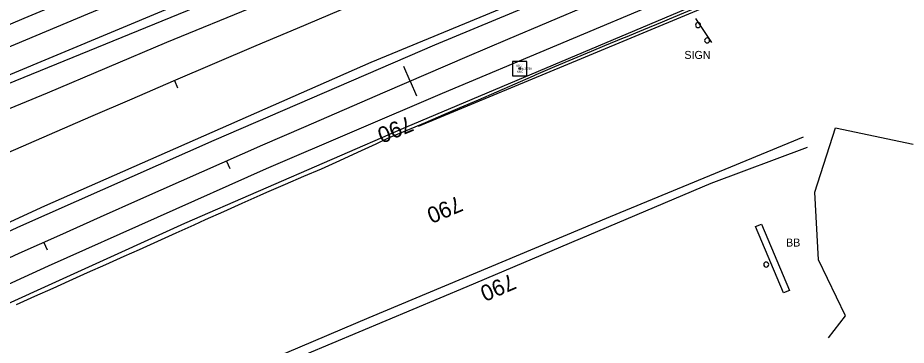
# Model space of a CAD drawing. Extents: x 1901471 to 1963503, y 756461 to 799997.
# Drawn here: x 1905145.4 to 1905589.4, y 758694.4 to 758857.7 of the extents above; entities that cross this region are included whole.
import ezdxf

# ---------------------------------------------------------------- set-up
doc = ezdxf.new("R2010")
doc.units = 0
for name, color, linetype in [('Default', 7, 'Continuous'), ('RD_DTM_BkLn1', 7, 'Continuous'), ('RD_EX_Bldg', 7, 'Continuous'), ('RD_EX_Driveway', 7, 'Continuous'), ('RD_EX_Fence_Other', 7, 'Continuous'), ('RD_EX_GuardRail', 7, 'Continuous'), ('RD_EX_Road', 7, 'Continuous'), ('RD_EX_Road_txCode', 7, 'Continuous'), ('RD_EX_VEG', 7, 'Continuous'), ('RD_HC_Cl', 7, 'Continuous'), ('RD_HC_Data_Tic', 7, 'Continuous'), ('RD_HC_Survey', 7, 'Continuous'), ('RD_HC_TX_Sta50', 7, 'Continuous'), ('RD_HC_txCode', 7, 'Continuous'), ('RD_SMD_Locator', 7, 'Continuous')]:
    doc.layers.add(name, color=color, linetype=linetype)

# ---------------------------------------------------------------- blocks, each defined once
blk = doc.blocks.new('SIGNPOST')
at = {"layer": 'Default'}
for start, end in [(90, 270), (270, 90)]:
    blk.add_arc((0, 0), 0.127, start, end, dxfattribs=at)

msp = doc.modelspace()

# ---------------------------------------------------------------- linework, layer by layer
at = {"layer": 'RD_DTM_BkLn1'}
for points in [[(1905449.13, 758848.09), (1905458.37, 758851.93), (1905467.6, 758855.76), (1905471.12, 758857.23), (1905480.35, 758861.07), (1905489.59, 758864.92), (1905493.47, 758866.54), (1905502.71, 758870.34), (1905511.96, 758874.14), (1905516.47, 758876), (1905525.76, 758879.7), (1905535.05, 758883.4), (1905535.64, 758883.63), (1905544.9, 758887.39), (1905554.17, 758891.15), (1905561.63, 758894.17), (1905570.9, 758897.93), (1905580.17, 758901.69), (1905582.87, 758902.78), (1905592.15, 758906.51)], [(1905144.82, 758714.65), (1905153.93, 758718.76), (1905163.05, 758722.87), (1905171.15, 758726.51), (1905180.29, 758730.58), (1905189.42, 758734.65), (1905198.55, 758738.72), (1905206.29, 758742.17), (1905215.41, 758746.27), (1905224.52, 758750.38), (1905233.64, 758754.49), (1905239.26, 758757.02), (1905248.39, 758761.11), (1905257.51, 758765.2), (1905266.64, 758769.29), (1905269.98, 758770.79), (1905279.17, 758774.72), (1905288.37, 758778.64), (1905297.26, 758782.43), (1905306.35, 758786.59), (1905315.44, 758790.74), (1905324.54, 758794.9), (1905330.78, 758797.75), (1905339.99, 758801.66), (1905349.19, 758805.56), (1905358.4, 758809.47), (1905366.46, 758812.88), (1905375.63, 758816.87), (1905384.8, 758820.86), (1905393.97, 758824.85), (1905403.14, 758828.84), (1905404.56, 758829.46), (1905413.78, 758833.35), (1905422.99, 758837.24), (1905432.2, 758841.13), (1905438.8, 758843.91), (1905448.07, 758847.66), (1905449.13, 758848.09)]]:
    msp.add_lwpolyline(points, dxfattribs=at)
at = {"layer": 'RD_EX_Bldg'}
msp.add_lwpolyline([(1905484.19, 758857.44), (1905492.11, 758845.44)], dxfattribs=at)
msp.add_lwpolyline([(1905517.07, 758754.76), (1905531.02, 758721.64), (1905528.15, 758720.43), (1905514.19, 758753.55)], close=True, dxfattribs=at)
at = {"layer": 'RD_EX_Driveway'}
for points in [[(1905537.99, 758798.17), (1905441.53, 758758.34), (1905320.85, 758708.08), (1905169.69, 758643.9), (1905069.4, 758600.83)], [(1904608.49, 758434.92), (1904740.93, 758494.18), (1904812.91, 758530.05), (1904856.1, 758551.52), (1904903.37, 758573.84), (1904943.2, 758586.31), (1904968.63, 758592.19), (1905001.98, 758596.27), (1905029.09, 758594.83), (1905056.2, 758590.99), (1905068.68, 758592.43), (1905168.49, 758639.1), (1905262.06, 758678.45), (1905370.03, 758723.67), (1905491.92, 758775.14), (1905540.15, 758793.25)]]:
    msp.add_lwpolyline(points, dxfattribs=at)
at = {"layer": 'RD_EX_Fence_Other'}
msp.add_lwpolyline([(1904922.24, 758713.27), (1904940.51, 758722.99), (1904969.08, 758737.95), (1904998.03, 758751.56), (1905043.12, 758770.41), (1905087.82, 758789.75), (1905130.58, 758808.21), (1905160.31, 758820.26), (1905219.98, 758845.62), (1905264.68, 758863.89), (1905325.31, 758888.28), (1905382.84, 758911.8), (1905443.08, 758935.02), (1905504.3, 758959.12), (1905562.41, 758981.56), (1905623.24, 759004.3), (1905713.03, 759039.19), (1905817.39, 759078.93), (1905890.66, 759107.4), (1906024.74, 759158.14)], dxfattribs=at)
at = {"layer": 'RD_EX_GuardRail'}
msp.add_lwpolyline([(1905345.67, 758803.68), (1905429.1, 758838.31), (1905538.42, 758883.79), (1905619.41, 758916.58), (1905717.53, 758955.5), (1905817.23, 758994.07), (1905933.89, 759038.76), (1906032.02, 759075.57), (1906133.29, 759113.62), (1906265.7, 759165.13), (1906336.89, 759191.63), (1906372.39, 759205.62)], dxfattribs=at)
at = {"layer": 'RD_EX_Road'}
for points in [[(1904473.49, 758548.93), (1904500.44, 758562.26), (1904626.78, 758623.69), (1904737.52, 758676.91), (1904839.24, 758723.91), (1904945.68, 758771.12), (1905022.94, 758804.38), (1905148.69, 758857.6), (1905252.13, 758900.74), (1905376.17, 758950.53), (1905495.06, 758997.1), (1905586.91, 759033.58), (1905766.75, 759102.68), (1905898.94, 759153.33), (1906088.67, 759225.52)], [(1904439.72, 758506.86), (1904499.55, 758537.08), (1904621.2, 758596), (1904726.79, 758645.79), (1904851.26, 758703.95), (1904955.55, 758750.3), (1905112.64, 758817.47), (1905246.55, 758873.27), (1905389.05, 758930.57), (1905499.78, 758974.35), (1905628.12, 759023.92), (1905762.03, 759075.43), (1905900.23, 759127.57), (1906144.35, 759221.25)], [(1903672.83, 758077.8), (1903785.09, 758144.01), (1903851.74, 758183.4), (1903961.34, 758246.64), (1904053.46, 758297.44), (1904124.85, 758336.84), (1904194.16, 758373.72), (1904279.76, 758419.63), (1904379.88, 758471.32), (1904499.85, 758532.04), (1904656.83, 758608.02), (1904831.51, 758689.36), (1905038.39, 758781.42), (1905127.66, 758819.62), (1905303.64, 758891.51), (1905396.35, 758929.71), (1905570.17, 758997.31), (1905672.75, 759036.37), (1905899.8, 759123.07), (1906075.63, 759189.9)], [(1903629.25, 757935.1), (1903744.21, 758008.43), (1903839.03, 758066.36), (1903969.69, 758145.02), (1904044.66, 758189.76), (1904152.21, 758251.84), (1904232.21, 758297.32), (1904315.47, 758342.95), (1904410.88, 758395.84), (1904475.77, 758430.06), (1904499.77, 758442.8), (1904716.91, 758554.8), (1904840.53, 758616.18), (1904995.04, 758688.5), (1905159, 758763.82), (1905322.09, 758835.5), (1905449.14, 758888.08), (1905598.93, 758949.45), (1905763.32, 759013.62), (1905899.8, 759066.2), (1906068.03, 759131)], [(1906146.36, 759121.29), (1905900.23, 759028.43), (1905683.83, 758945.07), (1905509.3, 758874.76), (1905339.14, 758802.99), (1905228.72, 758755.05), (1905125.23, 758708.17), (1905011.45, 758655.76), (1904902.15, 758603.96), (1904794.64, 758551.66), (1904634.65, 758472), (1904568.65, 758437.49), (1904499.42, 758401.34), (1904387.32, 758341.09), (1904276.9, 758280.57), (1904172.52, 758222.06), (1904029.77, 758139.21), (1903914.76, 758070.52), (1903832.08, 758019.61), (1903783.86, 757989.97), (1903644.91, 757900.63)], [(1904474.58, 758424.58), (1904500.06, 758438.5), (1904571.41, 758475.4), (1904669.7, 758526.04), (1904802.33, 758591.93), (1904918.21, 758647.72), (1905024.65, 758697.73), (1905146.98, 758753.95), (1905243.55, 758796.66), (1905353.85, 758844.3), (1905502.36, 758905.89), (1905686.92, 758980.14), (1905898.52, 759061.69), (1905966.66, 759087.39)], [(1904425.69, 758372.13), (1904499.77, 758411.24), (1904668.84, 758499.22), (1904776.57, 758552.01), (1904918.64, 758621.33), (1905017.79, 758668.54), (1905160.71, 758733.99), (1905269.73, 758782.49), (1905357.72, 758820.05), (1905471.89, 758868.12), (1905613.52, 758924.99), (1905755.59, 758981.64), (1905858.17, 759020.06), (1905901.25, 759036.49), (1906001.55, 759075.38)]]:
    msp.add_lwpolyline(points, dxfattribs=at)
at = {"layer": 'RD_EX_VEG'}
msp.add_lwpolyline([(1905550.65, 758698.02), (1905559.08, 758708.94), (1905545.54, 758736.93), (1905543.73, 758770.79), (1905554.12, 758802.85), (1905592.94, 758794.72)], dxfattribs=at)
at = {"layer": 'RD_HC_Cl'}
for centre, radius, start, end in [((1909748.74, 747960.74), 11817.56, 110.89447, 124.793002), ((1909868.32, 747986.81), 11792.71, 110.903407, 124.881023), ((1909948.59, 748094.28), 11678.9, 110.901971, 124.84852)]:
    msp.add_arc(centre, radius, start, end, dxfattribs=at)
at = {"layer": 'RD_HC_Data_Tic'}
for p, q in [((1905341.51, 758826.08), (1905338.36, 758833.43)), ((1905223.75, 758826.37), (1905225.33, 758822.7)), ((1905341.51, 758826.08), (1905344.67, 758818.73)), ((1905249.79, 758786.24), (1905251.4, 758782.58)), ((1905158.42, 758745.62), (1905160.06, 758741.97))]:
    msp.add_line(p, q, dxfattribs=at)
at = {"layer": 'RD_HC_Survey'}
msp.add_lwpolyline([(1905399.82, 758835.89), (1905392.75, 758835.89), (1905392.75, 758828.82), (1905399.82, 758828.82)], close=True, dxfattribs=at)
msp.add_circle((1905396.29, 758832.36), 0.5, dxfattribs=at)
at = {"layer": 'RD_SMD_Locator'}
msp.add_circle((1905396.29, 758832.36), 0.001, dxfattribs=at)

# ---------------------------------------------------------------- block references
at = {"layer": 'RD_EX_Bldg', "xscale": 9.84251968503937, "yscale": 9.84251968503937}
for p in [(1905485.39, 758854.08), (1905489.95, 758846.4), (1905519.47, 758734.6)]:
    msp.add_blockref('SIGNPOST', p, dxfattribs=at)

# ---------------------------------------------------------------- texts
at = {"layer": 'RD_EX_Road'}
for s, p in [('SIGN', (1905478.57, 758837.19)), ('BB', (1905529.38, 758743.57))]:
    msp.add_text(s, height=4, dxfattribs=at).set_placement(p)
at = {"layer": 'RD_EX_Road_txCode'}
msp.add_text('440.750', height=1, dxfattribs=at).set_placement((1905397.29, 758831.86))
at = {"layer": 'RD_HC_TX_Sta50'}
for rotation, p in [(202.1555, (1905340.9, 758809)), (202.7085, (1905365.58, 758769.11)), (203.2335, (1905392.14, 758730.29))]:
    msp.add_text('790', height=8, rotation=rotation, dxfattribs=at).set_placement(p)
at = {"layer": 'RD_HC_txCode'}
for s, p in [('8007', (1905394.58, 758833.36)), ('MSC', (1905394.97, 758830.36))]:
    msp.add_text(s, height=1, dxfattribs=at).set_placement(p)

doc.saveas('drawing.dxf')
